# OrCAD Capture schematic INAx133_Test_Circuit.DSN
size A; title: INAx133 High-Speed, Precision DIFFERENCE AMPLIFIERS; rev: 1.1; note: Datasheet: SBOS115  EVM: N/A
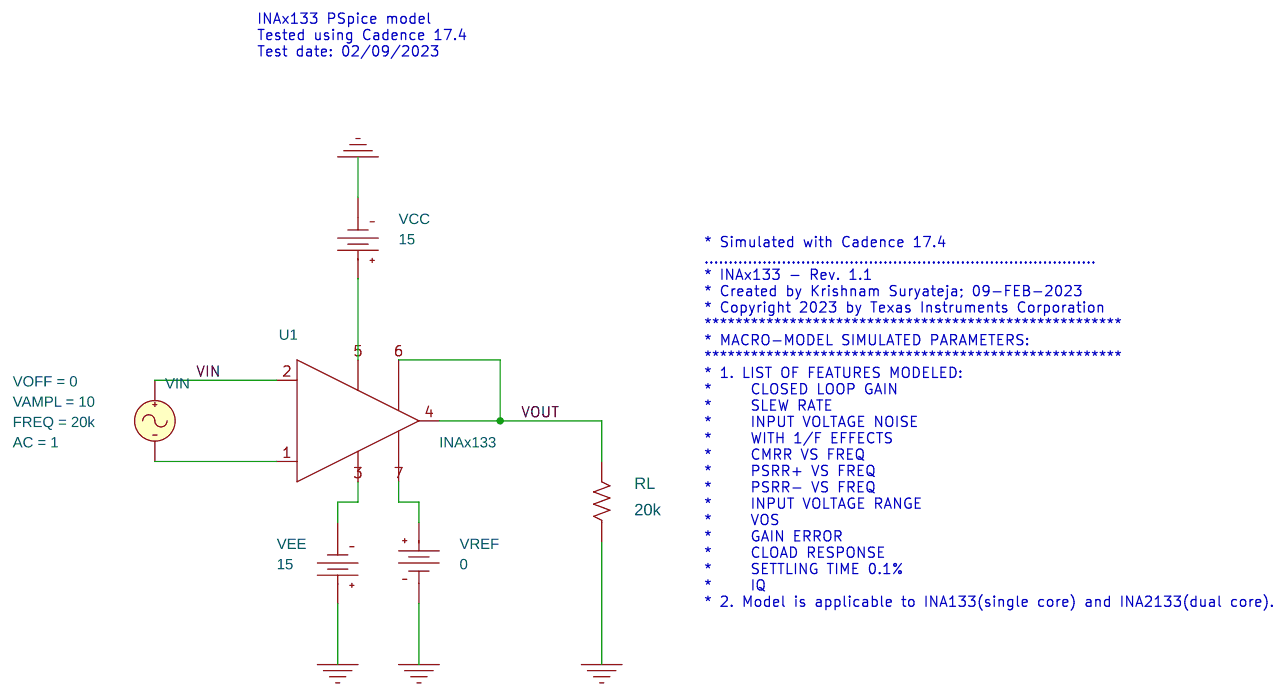
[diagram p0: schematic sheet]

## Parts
RL  20k  [AX/RC05]
U1  INAx133
VCC  VDC
VEE  VDC
VIN  VSIN
VREF  VDC

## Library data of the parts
RL = R
U1 = INAx133
VCC VEE = VDC: DC: 15
VIN = VSIN: AC: 1; FREQ: 20k; VAMPL: 10; VOFF: 0
VREF = VDC: DC: 0

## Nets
VIN: U1.2(-) VIN.1(+)
0: RL.1 VCC.1(-) VEE.0(+) VREF.1(-)
VOUT: RL.2 U1.4(OUT) U1.6(SENSE)
N14298623: U1.1(+) VIN.2(-)
N14298647: U1.3(V-) VEE.1(-)
N14298653: U1.7(REF) VREF.0(+)
N14298948: U1.5(V+) VCC.0(+)

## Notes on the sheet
- INAx133 PSpice model
  Tested using Cadence 17.4
  Test date: 02/09/2023
- * Simulated with Cadence 17.4
  .................................................................................
  * INAx133 - Rev. 1.1
  * Created by Krishnam Suryateja; 09-FEB-2023
  * Copyright 2023 by Texas Instruments Corporation
  ******************************************************
  * MACRO-MODEL SIMULATED PARAMETERS:
  ******************************************************
  * 1. LIST OF FEATURES MODELED:
  *     CLOSED LOOP GAIN
  *     SLEW RATE
  *     INPUT VOLTAGE NOISE
  *     WITH 1/F EFFECTS
  *     CMRR VS FREQ
  *     PSRR+ VS FREQ
  *     PSRR- VS FREQ
  *     INPUT VOLTAGE RANGE
  *     VOS
  *     GAIN ERROR
  *     CLOAD RESPONSE
  *     SETTLING TIME 0.1%
  *     IQ
  * 2. Model is applicable to INA133(single core) and INA2133(dual core).
